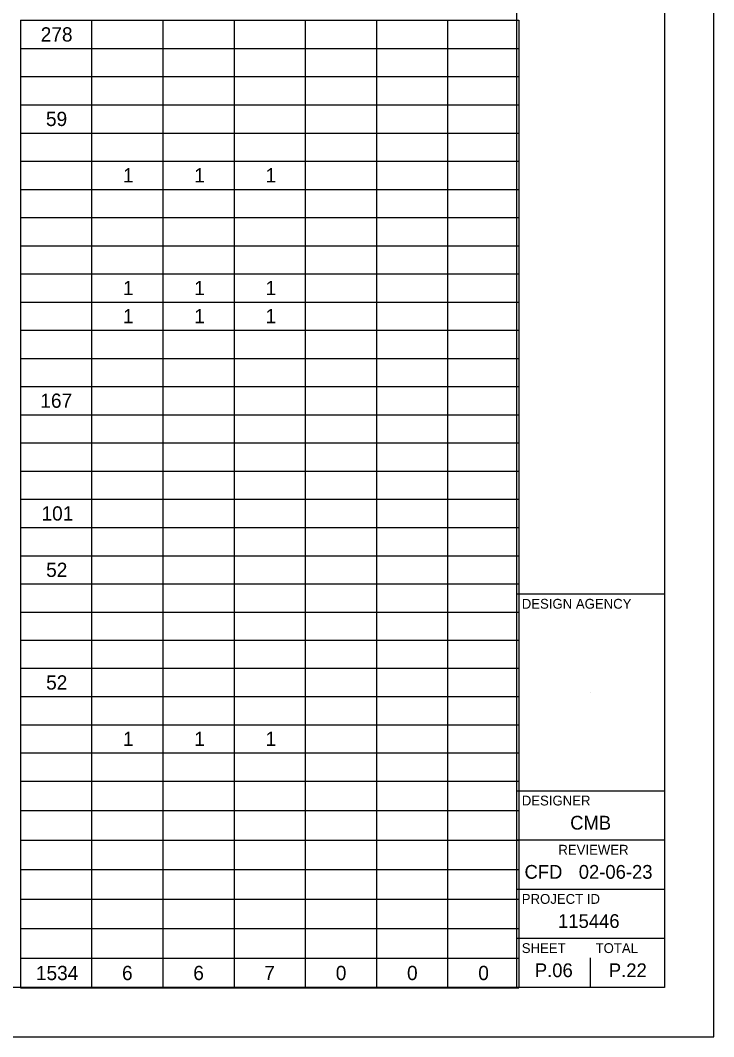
# Model space of a CAD drawing. Extents: x 0 to 34, y 0 to 22.
# Drawn here: x 26.95 to 34, y 0 to 10.33 of the extents above; entities that cross this region are included whole.
import ezdxf

# ---------------------------------------------------------------- set-up
doc = ezdxf.new("R2010")
doc.units = 0
for name, color, linetype in [('Default', 7, 'Continuous'), ('SH_Border', 7, 'Continuous'), ('SH_Cut_Line', 7, 'Continuous'), ('SH_Data', 7, 'Continuous')]:
    doc.layers.add(name, color=color, linetype=linetype)

msp = doc.modelspace()

# ---------------------------------------------------------------- linework, layer by layer
at = {"layer": 'Default'}
for p, q in [((26.955, 10.331), (27.679, 10.331)), ((26.955, 10.331), (26.955, 10.044)), ((27.679, 10.331), (29.85, 10.331)), ((27.679, 10.331), (27.679, 10.044)), ((28.402, 10.331), (28.402, 10.044)), ((29.126, 10.331), (29.126, 10.044)), ((29.85, 10.331), (30.574, 10.331)), ((29.85, 10.331), (29.85, 10.044)), ((30.574, 10.331), (31.297, 10.331)), ((30.574, 10.331), (30.574, 10.044)), ((31.297, 10.331), (32.021, 10.331)), ((31.297, 10.331), (31.297, 10.044)), ((32.021, 10.331), (32.021, 10.044)), ((26.955, 10.044), (27.679, 10.044)), ((26.955, 10.044), (26.955, 9.758)), ((27.679, 10.044), (29.85, 10.044)), ((27.679, 10.044), (27.679, 9.758)), ((28.402, 10.044), (28.402, 9.758)), ((29.126, 10.044), (29.126, 9.758)), ((29.85, 10.044), (30.574, 10.044)), ((29.85, 10.044), (29.85, 9.758)), ((30.574, 10.044), (31.297, 10.044)), ((30.574, 10.044), (30.574, 9.758)), ((31.297, 10.044), (32.021, 10.044)), ((31.297, 10.044), (31.297, 9.758)), ((32.021, 10.044), (32.021, 9.758)), ((26.955, 9.758), (27.679, 9.758)), ((26.955, 9.758), (26.955, 9.471)), ((27.679, 9.758), (29.85, 9.758)), ((27.679, 9.758), (27.679, 9.471)), ((28.402, 9.758), (28.402, 9.471)), ((29.126, 9.758), (29.126, 9.471)), ((29.85, 9.758), (30.574, 9.758)), ((29.85, 9.758), (29.85, 9.471)), ((30.574, 9.758), (31.297, 9.758)), ((30.574, 9.758), (30.574, 9.471)), ((31.297, 9.758), (32.021, 9.758)), ((31.297, 9.758), (31.297, 9.471)), ((32.021, 9.758), (32.021, 9.471)), ((26.955, 9.471), (27.679, 9.471)), ((26.955, 9.471), (26.955, 9.185)), ((27.679, 9.471), (29.85, 9.471)), ((27.679, 9.471), (27.679, 9.185)), ((28.402, 9.471), (28.402, 9.185)), ((29.126, 9.471), (29.126, 9.185)), ((29.85, 9.471), (30.574, 9.471)), ((29.85, 9.471), (29.85, 9.185)), ((30.574, 9.471), (31.297, 9.471)), ((30.574, 9.471), (30.574, 9.185)), ((31.297, 9.471), (32.021, 9.471)), ((31.297, 9.471), (31.297, 9.185)), ((32.021, 9.471), (32.021, 9.185)), ((26.955, 9.185), (27.679, 9.185)), ((26.955, 9.185), (26.955, 8.899)), ((27.679, 9.185), (29.85, 9.185)), ((27.679, 9.185), (27.679, 8.899)), ((28.402, 9.185), (28.402, 8.899)), ((29.126, 9.185), (29.126, 8.899)), ((29.85, 9.185), (30.574, 9.185)), ((29.85, 9.185), (29.85, 8.899)), ((30.574, 9.185), (31.297, 9.185)), ((30.574, 9.185), (30.574, 8.899)), ((31.297, 9.185), (32.021, 9.185)), ((31.297, 9.185), (31.297, 8.899)), ((32.021, 9.185), (32.021, 8.899)), ((26.955, 8.899), (27.679, 8.899)), ((26.955, 8.899), (26.955, 8.612)), ((27.679, 8.899), (29.85, 8.899)), ((27.679, 8.899), (27.679, 8.612)), ((28.402, 8.899), (28.402, 8.612)), ((29.126, 8.899), (29.126, 8.612)), ((29.85, 8.899), (30.574, 8.899)), ((29.85, 8.899), (29.85, 8.612)), ((30.574, 8.899), (31.297, 8.899)), ((30.574, 8.899), (30.574, 8.612)), ((31.297, 8.899), (32.021, 8.899)), ((31.297, 8.899), (31.297, 8.612)), ((32.021, 8.899), (32.021, 8.612)), ((26.955, 8.612), (27.679, 8.612)), ((26.955, 8.612), (26.955, 8.326)), ((27.679, 8.612), (29.85, 8.612)), ((27.679, 8.612), (27.679, 8.326)), ((28.402, 8.612), (28.402, 8.326)), ((29.126, 8.612), (29.126, 8.326)), ((29.85, 8.612), (30.574, 8.612)), ((29.85, 8.612), (29.85, 8.326)), ((30.574, 8.612), (31.297, 8.612)), ((30.574, 8.612), (30.574, 8.326)), ((31.297, 8.612), (32.021, 8.612)), ((31.297, 8.612), (31.297, 8.326)), ((32.021, 8.612), (32.021, 8.326)), ((26.955, 8.326), (27.679, 8.326)), ((26.955, 8.326), (26.955, 8.039)), ((27.679, 8.326), (29.85, 8.326)), ((27.679, 8.326), (27.679, 8.039)), ((28.402, 8.326), (28.402, 8.039)), ((29.126, 8.326), (29.126, 8.039)), ((29.85, 8.326), (30.574, 8.326)), ((29.85, 8.326), (29.85, 8.039)), ((30.574, 8.326), (31.297, 8.326)), ((30.574, 8.326), (30.574, 8.039)), ((31.297, 8.326), (32.021, 8.326)), ((31.297, 8.326), (31.297, 8.039)), ((32.021, 8.326), (32.021, 8.039)), ((26.955, 8.039), (27.679, 8.039)), ((26.955, 8.039), (26.955, 7.753)), ((27.679, 8.039), (29.85, 8.039)), ((27.679, 8.039), (27.679, 7.753)), ((28.402, 8.039), (28.402, 7.753)), ((29.126, 8.039), (29.126, 7.753)), ((29.85, 8.039), (30.574, 8.039)), ((29.85, 8.039), (29.85, 7.753)), ((30.574, 8.039), (31.297, 8.039)), ((30.574, 8.039), (30.574, 7.753)), ((31.297, 8.039), (32.021, 8.039)), ((31.297, 8.039), (31.297, 7.753)), ((32.021, 8.039), (32.021, 7.753)), ((26.955, 7.753), (27.679, 7.753)), ((26.955, 7.753), (26.955, 7.467)), ((27.679, 7.753), (29.85, 7.753)), ((27.679, 7.753), (27.679, 7.467)), ((28.402, 7.753), (28.402, 7.467)), ((29.126, 7.753), (29.126, 7.467)), ((29.85, 7.753), (30.574, 7.753)), ((29.85, 7.753), (29.85, 7.467)), ((30.574, 7.753), (31.297, 7.753)), ((30.574, 7.753), (30.574, 7.467)), ((31.297, 7.753), (32.021, 7.753)), ((31.297, 7.753), (31.297, 7.467)), ((32.021, 7.753), (32.021, 7.467)), ((26.955, 7.467), (27.679, 7.467)), ((26.955, 7.467), (26.955, 7.18)), ((27.679, 7.467), (29.85, 7.467)), ((27.679, 7.467), (27.679, 7.18)), ((28.402, 7.467), (28.402, 7.18)), ((29.126, 7.467), (29.126, 7.18)), ((29.85, 7.467), (30.574, 7.467)), ((29.85, 7.467), (29.85, 7.18)), ((30.574, 7.467), (31.297, 7.467)), ((30.574, 7.467), (30.574, 7.18)), ((31.297, 7.467), (32.021, 7.467)), ((31.297, 7.467), (31.297, 7.18)), ((32.021, 7.467), (32.021, 7.18)), ((26.955, 7.18), (27.679, 7.18)), ((26.955, 7.18), (26.955, 6.894)), ((27.679, 7.18), (29.85, 7.18)), ((27.679, 7.18), (27.679, 6.894)), ((28.402, 7.18), (28.402, 6.894)), ((29.126, 7.18), (29.126, 6.894)), ((29.85, 7.18), (30.574, 7.18)), ((29.85, 7.18), (29.85, 6.894)), ((30.574, 7.18), (31.297, 7.18)), ((30.574, 7.18), (30.574, 6.894)), ((31.297, 7.18), (32.021, 7.18)), ((31.297, 7.18), (31.297, 6.894)), ((32.021, 7.18), (32.021, 6.894)), ((26.955, 6.894), (27.679, 6.894)), ((26.955, 6.894), (26.955, 6.607)), ((27.679, 6.894), (29.85, 6.894)), ((27.679, 6.894), (27.679, 6.607)), ((28.402, 6.894), (28.402, 6.607)), ((29.126, 6.894), (29.126, 6.607)), ((29.85, 6.894), (30.574, 6.894)), ((29.85, 6.894), (29.85, 6.607)), ((30.574, 6.894), (31.297, 6.894)), ((30.574, 6.894), (30.574, 6.607)), ((31.297, 6.894), (32.021, 6.894)), ((31.297, 6.894), (31.297, 6.607)), ((32.021, 6.894), (32.021, 6.607)), ((26.955, 6.607), (27.679, 6.607)), ((26.955, 6.607), (26.955, 6.321)), ((27.679, 6.607), (29.85, 6.607)), ((27.679, 6.607), (27.679, 6.321)), ((28.402, 6.607), (28.402, 6.321)), ((29.126, 6.607), (29.126, 6.321)), ((29.85, 6.607), (30.574, 6.607)), ((29.85, 6.607), (29.85, 6.321)), ((30.574, 6.607), (31.297, 6.607)), ((30.574, 6.607), (30.574, 6.321)), ((31.297, 6.607), (32.021, 6.607)), ((31.297, 6.607), (31.297, 6.321)), ((32.021, 6.607), (32.021, 6.321)), ((26.955, 6.321), (27.679, 6.321)), ((26.955, 6.321), (26.955, 6.035)), ((27.679, 6.321), (29.85, 6.321)), ((27.679, 6.321), (27.679, 6.035)), ((28.402, 6.321), (28.402, 6.035)), ((29.126, 6.321), (29.126, 6.035)), ((29.85, 6.321), (30.574, 6.321)), ((29.85, 6.321), (29.85, 6.035)), ((30.574, 6.321), (31.297, 6.321)), ((30.574, 6.321), (30.574, 6.035)), ((31.297, 6.321), (32.021, 6.321)), ((31.297, 6.321), (31.297, 6.035)), ((32.021, 6.321), (32.021, 6.035)), ((26.955, 6.035), (27.679, 6.035)), ((26.955, 6.035), (26.955, 5.748)), ((27.679, 6.035), (29.85, 6.035)), ((27.679, 6.035), (27.679, 5.748)), ((28.402, 6.035), (28.402, 5.748)), ((29.126, 6.035), (29.126, 5.748)), ((29.85, 6.035), (30.574, 6.035)), ((29.85, 6.035), (29.85, 5.748)), ((30.574, 6.035), (31.297, 6.035)), ((30.574, 6.035), (30.574, 5.748)), ((31.297, 6.035), (32.021, 6.035)), ((31.297, 6.035), (31.297, 5.748)), ((32.021, 6.035), (32.021, 5.748)), ((26.955, 5.748), (27.679, 5.748)), ((26.955, 5.748), (26.955, 5.462)), ((27.679, 5.748), (29.85, 5.748)), ((27.679, 5.748), (27.679, 5.462)), ((28.402, 5.748), (28.402, 5.462)), ((29.126, 5.748), (29.126, 5.462)), ((29.85, 5.748), (30.574, 5.748)), ((29.85, 5.748), (29.85, 5.462)), ((30.574, 5.748), (31.297, 5.748)), ((30.574, 5.748), (30.574, 5.462)), ((31.297, 5.748), (32.021, 5.748)), ((31.297, 5.748), (31.297, 5.462)), ((32.021, 5.748), (32.021, 5.462)), ((26.955, 5.462), (27.679, 5.462)), ((26.955, 5.462), (26.955, 5.175)), ((27.679, 5.462), (29.85, 5.462)), ((27.679, 5.462), (27.679, 5.175)), ((28.402, 5.462), (28.402, 5.175)), ((29.126, 5.462), (29.126, 5.175)), ((29.85, 5.462), (30.574, 5.462)), ((29.85, 5.462), (29.85, 5.175)), ((30.574, 5.462), (31.297, 5.462)), ((30.574, 5.462), (30.574, 5.175)), ((31.297, 5.462), (32.021, 5.462)), ((31.297, 5.462), (31.297, 5.175)), ((32.021, 5.462), (32.021, 5.175)), ((26.955, 5.175), (27.679, 5.175)), ((26.955, 5.175), (26.955, 4.603)), ((27.679, 5.175), (29.85, 5.175)), ((27.679, 5.175), (27.679, 4.603)), ((28.402, 5.175), (28.402, 4.603)), ((29.126, 5.175), (29.126, 4.603)), ((29.85, 5.175), (30.574, 5.175)), ((29.85, 5.175), (29.85, 4.603)), ((30.574, 5.175), (31.297, 5.175)), ((30.574, 5.175), (30.574, 4.603)), ((31.297, 5.175), (32.021, 5.175)), ((31.297, 5.175), (31.297, 4.603)), ((32.021, 5.175), (32.021, 4.603)), ((26.955, 4.889), (27.679, 4.889)), ((27.679, 4.889), (29.85, 4.889)), ((29.85, 4.889), (30.574, 4.889)), ((30.574, 4.889), (31.297, 4.889)), ((31.297, 4.889), (32.021, 4.889)), ((26.955, 4.603), (27.679, 4.603)), ((26.955, 4.603), (26.955, 4.316)), ((27.679, 4.603), (29.85, 4.603)), ((27.679, 4.603), (27.679, 4.316)), ((28.402, 4.603), (28.402, 4.316)), ((29.126, 4.603), (29.126, 4.316)), ((29.85, 4.603), (30.574, 4.603)), ((29.85, 4.603), (29.85, 4.316)), ((30.574, 4.603), (31.297, 4.603)), ((30.574, 4.603), (30.574, 4.316)), ((31.297, 4.603), (32.021, 4.603)), ((31.297, 4.603), (31.297, 4.316)), ((32.021, 4.603), (32.021, 4.316)), ((26.955, 4.316), (27.679, 4.316)), ((26.955, 4.316), (26.955, 4.03)), ((27.679, 4.316), (29.85, 4.316)), ((27.679, 4.316), (27.679, 4.03)), ((28.402, 4.316), (28.402, 4.03)), ((29.126, 4.316), (29.126, 4.03)), ((29.85, 4.316), (30.574, 4.316)), ((29.85, 4.316), (29.85, 4.03)), ((30.574, 4.316), (31.297, 4.316)), ((30.574, 4.316), (30.574, 4.03)), ((31.297, 4.316), (32.021, 4.316)), ((31.297, 4.316), (31.297, 4.03)), ((32.021, 4.316), (32.021, 4.03)), ((26.955, 4.03), (27.679, 4.03)), ((26.955, 4.03), (26.955, 3.744)), ((27.679, 4.03), (29.85, 4.03)), ((27.679, 4.03), (27.679, 3.744)), ((28.402, 4.03), (28.402, 3.744)), ((29.126, 4.03), (29.126, 3.744)), ((29.85, 4.03), (30.574, 4.03)), ((29.85, 4.03), (29.85, 3.744)), ((30.574, 4.03), (31.297, 4.03)), ((30.574, 4.03), (30.574, 3.744)), ((31.297, 4.03), (32.021, 4.03)), ((31.297, 4.03), (31.297, 3.744)), ((32.021, 4.03), (32.021, 3.744)), ((26.955, 3.744), (27.679, 3.744)), ((26.955, 3.744), (26.955, 3.171)), ((27.679, 3.744), (29.85, 3.744)), ((27.679, 3.744), (27.679, 3.171)), ((28.402, 3.744), (28.402, 3.171)), ((29.126, 3.744), (29.126, 3.171)), ((29.85, 3.744), (30.574, 3.744)), ((29.85, 3.744), (29.85, 3.171)), ((30.574, 3.744), (31.297, 3.744)), ((30.574, 3.744), (30.574, 3.171)), ((31.297, 3.744), (32.021, 3.744)), ((31.297, 3.744), (31.297, 3.171)), ((32.021, 3.744), (32.021, 3.171)), ((26.955, 3.457), (27.679, 3.457)), ((27.679, 3.457), (29.85, 3.457)), ((29.85, 3.457), (30.574, 3.457)), ((30.574, 3.457), (31.297, 3.457)), ((31.297, 3.457), (32.021, 3.457)), ((26.955, 3.171), (27.679, 3.171)), ((26.955, 3.171), (26.955, 2.884)), ((27.679, 3.171), (29.85, 3.171)), ((27.679, 3.171), (27.679, 2.884)), ((28.402, 3.171), (28.402, 2.884)), ((29.126, 3.171), (29.126, 2.884)), ((29.85, 3.171), (30.574, 3.171)), ((29.85, 3.171), (29.85, 2.884)), ((30.574, 3.171), (31.297, 3.171)), ((30.574, 3.171), (30.574, 2.884)), ((31.297, 3.171), (32.021, 3.171)), ((31.297, 3.171), (31.297, 2.884)), ((32.021, 3.171), (32.021, 2.884)), ((26.955, 2.884), (27.679, 2.884)), ((26.955, 2.884), (26.955, 2.598)), ((27.679, 2.884), (29.85, 2.884)), ((27.679, 2.884), (27.679, 2.598)), ((28.402, 2.884), (28.402, 2.598)), ((29.126, 2.884), (29.126, 2.598)), ((29.85, 2.884), (30.574, 2.884)), ((29.85, 2.884), (29.85, 2.598)), ((30.574, 2.884), (31.297, 2.884)), ((30.574, 2.884), (30.574, 2.598)), ((31.297, 2.884), (32.021, 2.884)), ((31.297, 2.884), (31.297, 2.598)), ((32.021, 2.884), (32.021, 2.598)), ((26.955, 2.598), (27.679, 2.598)), ((26.955, 2.598), (26.955, 2.298)), ((27.679, 2.598), (29.85, 2.598)), ((27.679, 2.598), (27.679, 2.298)), ((28.402, 2.598), (28.402, 2.298)), ((29.126, 2.598), (29.126, 2.298)), ((29.85, 2.598), (30.574, 2.598)), ((29.85, 2.598), (29.85, 2.298)), ((30.574, 2.598), (31.297, 2.598)), ((30.574, 2.598), (30.574, 2.298)), ((31.297, 2.598), (32.021, 2.598)), ((31.297, 2.598), (31.297, 2.298)), ((32.021, 2.598), (32.021, 2.298)), ((26.955, 2.298), (27.679, 2.298)), ((26.955, 2.298), (26.955, 1.398)), ((27.679, 2.298), (29.85, 2.298)), ((27.679, 2.298), (27.679, 1.398)), ((28.402, 2.298), (28.402, 1.398)), ((29.126, 2.298), (29.126, 1.398)), ((29.85, 2.298), (30.574, 2.298)), ((29.85, 2.298), (29.85, 1.398)), ((30.574, 2.298), (31.297, 2.298)), ((30.574, 2.298), (30.574, 1.398)), ((31.297, 2.298), (32.021, 2.298)), ((31.297, 2.298), (31.297, 1.398)), ((32.021, 2.298), (32.021, 1.398)), ((26.955, 1.998), (27.679, 1.998)), ((27.679, 1.998), (29.85, 1.998)), ((29.85, 1.998), (30.574, 1.998)), ((30.574, 1.998), (31.297, 1.998)), ((31.297, 1.998), (32.021, 1.998)), ((26.955, 1.698), (27.679, 1.698)), ((27.679, 1.698), (29.85, 1.698)), ((29.85, 1.698), (30.574, 1.698)), ((30.574, 1.698), (31.297, 1.698)), ((31.297, 1.698), (32.021, 1.698)), ((26.955, 1.398), (27.679, 1.398)), ((26.955, 1.398), (26.955, 0.798)), ((27.679, 1.398), (29.85, 1.398)), ((27.679, 1.398), (27.679, 0.798)), ((28.402, 1.398), (28.402, 0.798)), ((29.126, 1.398), (29.126, 0.798)), ((29.85, 1.398), (30.574, 1.398)), ((29.85, 1.398), (29.85, 0.798)), ((30.574, 1.398), (31.297, 1.398)), ((30.574, 1.398), (30.574, 0.798)), ((31.297, 1.398), (32.021, 1.398)), ((31.297, 1.398), (31.297, 0.798)), ((32.021, 1.398), (32.021, 0.798)), ((26.955, 1.098), (27.679, 1.098)), ((27.679, 1.098), (29.85, 1.098)), ((29.85, 1.098), (30.574, 1.098)), ((30.574, 1.098), (31.297, 1.098)), ((31.297, 1.098), (32.021, 1.098)), ((26.955, 0.798), (27.679, 0.798)), ((26.955, 0.798), (26.955, 0.498)), ((27.679, 0.798), (29.85, 0.798)), ((27.679, 0.798), (27.679, 0.498)), ((28.402, 0.798), (28.402, 0.498)), ((29.126, 0.798), (29.126, 0.498)), ((29.85, 0.798), (30.574, 0.798)), ((29.85, 0.798), (29.85, 0.498)), ((30.574, 0.798), (31.297, 0.798)), ((30.574, 0.798), (30.574, 0.498)), ((31.297, 0.798), (32.021, 0.798)), ((31.297, 0.798), (31.297, 0.498)), ((32.021, 0.798), (32.021, 0.498)), ((26.955, 0.498), (27.679, 0.498)), ((27.679, 0.498), (29.85, 0.498)), ((29.85, 0.498), (30.574, 0.498)), ((30.574, 0.498), (31.297, 0.498)), ((31.297, 0.498), (32.021, 0.498))]:
    msp.add_line(p, q, dxfattribs=at)
at = {"layer": 'SH_Border'}
for p, q in [((32, 0.5), (32, 21.5)), ((32, 4.5), (33.5, 4.5)), ((32, 2.5), (33.5, 2.5)), ((32, 2), (33.5, 2)), ((32, 1.5), (33.5, 1.5)), ((32, 1), (33.5, 1))]:
    msp.add_line(p, q, dxfattribs=at)
msp.add_lwpolyline([(1.5, 21.5), (33.5, 21.5), (33.5, 0.5), (1.5, 0.5)], close=True, dxfattribs=at)
at = {"layer": 'SH_Cut_Line'}
msp.add_lwpolyline([(0, 0), (34, 0), (34, 22), (0, 22)], close=True, dxfattribs=at)
at = {"layer": 'SH_Data'}
for p, q in [((32.75, 3.5), (32.75, 3.5)), ((32.75, 0.5), (32.75, 0.8)), ((32.375, 0.675), (32.375, 0.675))]:
    msp.add_line(p, q, dxfattribs=at)

# ---------------------------------------------------------------- texts
at = {"layer": 'Default'}
for s, height, p in [('278', 0.1449, (27.162, 10.115)), ('59', 0.1449, (27.215, 9.256)), ('1', 0.145, (27.998, 8.683)), ('1', 0.145, (28.722, 8.683)), ('1', 0.145, (29.446, 8.683)), ('1', 0.145, (27.998, 7.537)), ('1', 0.145, (28.722, 7.537)), ('1', 0.145, (29.446, 7.537)), ('1', 0.145, (27.998, 7.251)), ('1', 0.145, (28.722, 7.251)), ('1', 0.145, (29.446, 7.251)), ('167', 0.1449, (27.158, 6.392)), ('101', 0.1449, (27.17, 5.246)), ('52', 0.1449, (27.217, 4.673)), ('52', 0.1449, (27.217, 3.528)), ('1', 0.145, (27.998, 2.955)), ('1', 0.145, (28.722, 2.955)), ('1', 0.145, (29.446, 2.955)), ('1534', 0.1449, (27.113, 0.575)), ('6', 0.145, (27.988, 0.575)), ('6', 0.145, (28.712, 0.575)), ('7', 0.145, (29.433, 0.575)), ('0', 0.145, (30.16, 0.575)), ('0', 0.145, (30.884, 0.575)), ('0', 0.145, (31.608, 0.575))]:
    msp.add_text(s, height=height, dxfattribs=at).set_placement(p)
at = {"layer": 'SH_Data'}
for s, height, p in [('DESIGN AGENCY', 0.1, (32.05, 4.35)), ('DESIGNER', 0.1, (32.05, 2.35)), ('CMB', 0.14, (32.542, 2.105)), ('REVIEWER', 0.1, (32.422, 1.85)), ('CFD', 0.14, (32.078, 1.605)), ('02-06-23', 0.14, (32.629, 1.605)), ('PROJECT ID', 0.1, (32.05, 1.35)), ('115446', 0.14, (32.419, 1.105)), ('SHEET', 0.1, (32.05, 0.85)), ('TOTAL', 0.1, (32.8, 0.85)), ('P.06', 0.14, (32.183, 0.605)), ('P.22', 0.14, (32.935, 0.605))]:
    msp.add_text(s, height=height, dxfattribs=at).set_placement(p)

doc.saveas('drawing.dxf')
